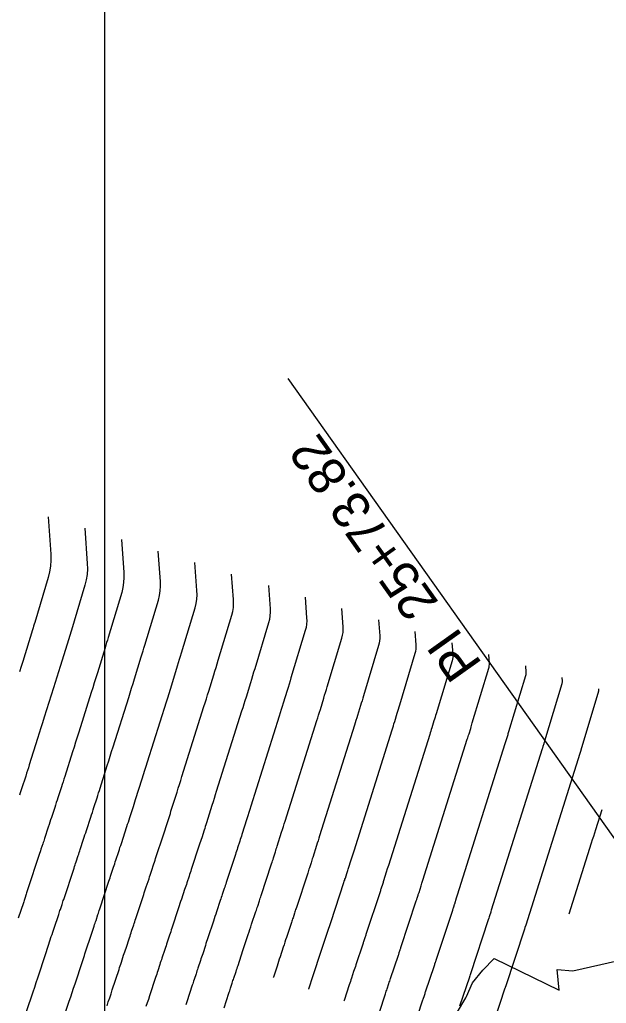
# Model space of a CAD drawing. Extents: x 1710723 to 1713003, y 548603 to 551142.
# Drawn here: x 1712348 to 1712442.1, y 549743.8 to 549901.4 of the extents above; entities that cross this region are included whole.
import ezdxf

# ---------------------------------------------------------------- set-up
doc = ezdxf.new("R2010")
doc.units = 0
for name, color, linetype in [('R_Contours', 7, 'Continuous'), ('R_Horz Alg Annot', 7, 'Continuous'), ('R_MOT', 7, 'Continuous'), ('R_No Plot', 7, 'Continuous')]:
    doc.layers.add(name, color=color, linetype=linetype)

msp = doc.modelspace()

# ---------------------------------------------------------------- linework, layer by layer
at = {"layer": 'R_Contours'}
for points in [[(1712352.55, 549821.78), (1712352.99, 549815.75), (1712353.02, 549814.8), (1712352.96, 549813.87), (1712352.81, 549812.95), (1712352.58, 549812.03), (1712350.42, 549804.83), (1712350.33, 549804.54), (1712350.24, 549804.25), (1712350.15, 549803.96), (1712350.06, 549803.67), (1712348.5, 549798.6), (1712348.24, 549797.76), (1712347.98, 549796.92)], [(1712358.44, 549819.94), (1712358.85, 549814.3), (1712358.88, 549813.41), (1712358.82, 549812.54), (1712358.68, 549811.68), (1712358.47, 549810.82), (1712356.3, 549803.62), (1712356.2, 549803.27), (1712356.09, 549802.93), (1712355.99, 549802.58), (1712355.88, 549802.23), (1712354.5, 549797.77), (1712354.24, 549796.91), (1712353.97, 549796.05), (1712353.7, 549795.2), (1712353.43, 549794.34), (1712351.95, 549789.64), (1712351.68, 549788.78), (1712351.41, 549787.93), (1712351.14, 549787.08), (1712350.87, 549786.23), (1712349.54, 549782.02), (1712349.4, 549781.57), (1712349.26, 549781.12), (1712349.12, 549780.67), (1712348.97, 549780.22), (1712348.32, 549778.19), (1712348.21, 549777.85), (1712348.1, 549777.52), (1712347.99, 549777.19)], [(1712364.32, 549818.1), (1712364.71, 549812.85), (1712364.73, 549812.02), (1712364.68, 549811.21), (1712364.56, 549810.41), (1712364.36, 549809.61), (1712362.19, 549802.41), (1712362.07, 549802), (1712361.94, 549801.6), (1712361.82, 549801.19), (1712361.69, 549800.78), (1712360.46, 549796.79), (1712360.22, 549795.99), (1712359.97, 549795.19), (1712359.72, 549794.39), (1712359.47, 549793.59), (1712357.47, 549787.26), (1712357.22, 549786.47), (1712356.97, 549785.67), (1712356.72, 549784.88), (1712356.47, 549784.09), (1712355.23, 549780.16), (1712355.09, 549779.74), (1712354.96, 549779.32), (1712354.83, 549778.9), (1712354.69, 549778.48), (1712354.14, 549776.75), (1712354.01, 549776.36), (1712353.88, 549775.97), (1712353.75, 549775.58), (1712353.63, 549775.18), (1712353.1, 549773.59), (1712352.97, 549773.21), (1712352.85, 549772.83), (1712352.72, 549772.45), (1712352.6, 549772.07), (1712352, 549770.22), (1712351.93, 549770.01), (1712351.86, 549769.79), (1712351.79, 549769.58), (1712351.71, 549769.36), (1712351.42, 549768.5), (1712351.35, 549768.28), (1712351.28, 549768.07), (1712351.21, 549767.85), (1712351.14, 549767.64), (1712349.28, 549762.02), (1712349.22, 549761.85), (1712349.17, 549761.67), (1712349.11, 549761.5), (1712349.05, 549761.32), (1712348.83, 549760.63), (1712348.77, 549760.45), (1712348.71, 549760.28), (1712348.65, 549760.1), (1712348.6, 549759.93), (1712347.77, 549757.48)], [(1712348.84, 549741.77), (1712349.9, 549744.89), (1712350.15, 549745.65), (1712350.41, 549746.4), (1712350.66, 549747.16), (1712350.91, 549747.92), (1712352.2, 549751.81), (1712352.31, 549752.15), (1712352.42, 549752.49), (1712352.53, 549752.82), (1712352.64, 549753.16), (1712353.08, 549754.52), (1712353.2, 549754.86), (1712353.31, 549755.2), (1712353.42, 549755.54), (1712353.53, 549755.88), (1712354.27, 549758.07), (1712354.34, 549758.27), (1712354.4, 549758.47), (1712354.47, 549758.67), (1712354.54, 549758.87), (1712354.8, 549759.68), (1712354.86, 549759.88), (1712354.93, 549760.08), (1712355, 549760.28), (1712355.06, 549760.48), (1712356.72, 549765.5), (1712356.8, 549765.75), (1712356.89, 549766), (1712356.97, 549766.25), (1712357.05, 549766.5), (1712357.39, 549767.49), (1712357.47, 549767.74), (1712357.55, 549767.99), (1712357.63, 549768.24), (1712357.72, 549768.49), (1712358.24, 549770.1), (1712358.36, 549770.45), (1712358.47, 549770.81), (1712358.59, 549771.16), (1712358.7, 549771.51), (1712359.41, 549773.64), (1712359.53, 549774.03), (1712359.66, 549774.42), (1712359.79, 549774.8), (1712359.91, 549775.19), (1712360.41, 549776.75), (1712360.54, 549777.14), (1712360.66, 549777.52), (1712360.78, 549777.91), (1712360.91, 549778.3), (1712362.06, 549781.94), (1712362.29, 549782.68), (1712362.52, 549783.42), (1712362.75, 549784.15), (1712362.99, 549784.89), (1712365.5, 549792.84), (1712365.73, 549793.58), (1712365.96, 549794.33), (1712366.19, 549795.07), (1712366.42, 549795.81), (1712367.51, 549799.34), (1712367.65, 549799.8), (1712367.79, 549800.27), (1712367.94, 549800.73), (1712368.08, 549801.2), (1712370.24, 549808.4), (1712370.43, 549809.14), (1712370.55, 549809.88), (1712370.59, 549810.63), (1712370.57, 549811.39), (1712370.21, 549816.26)], [(1712354.98, 549741.3), (1712355.95, 549744.17), (1712356.19, 549744.87), (1712356.42, 549745.57), (1712356.66, 549746.26), (1712356.89, 549746.96), (1712358.07, 549750.53), (1712358.17, 549750.85), (1712358.27, 549751.16), (1712358.38, 549751.47), (1712358.48, 549751.78), (1712358.88, 549753.03), (1712358.98, 549753.34), (1712359.09, 549753.65), (1712359.19, 549753.96), (1712359.29, 549754.27), (1712359.94, 549756.2), (1712360.02, 549756.43), (1712360.1, 549756.66), (1712360.17, 549756.89), (1712360.25, 549757.11), (1712360.54, 549758.03), (1712360.62, 549758.26), (1712360.69, 549758.49), (1712360.77, 549758.72), (1712360.84, 549758.94), (1712362.31, 549763.37), (1712362.4, 549763.65), (1712362.49, 549763.93), (1712362.59, 549764.22), (1712362.68, 549764.5), (1712363.06, 549765.62), (1712363.15, 549765.9), (1712363.25, 549766.19), (1712363.34, 549766.47), (1712363.43, 549766.75), (1712363.88, 549768.13), (1712363.99, 549768.46), (1712364.09, 549768.78), (1712364.2, 549769.1), (1712364.31, 549769.43), (1712365.21, 549772.15), (1712365.32, 549772.51), (1712365.44, 549772.86), (1712365.56, 549773.22), (1712365.67, 549773.58), (1712366.13, 549775.01), (1712366.25, 549775.37), (1712366.36, 549775.73), (1712366.48, 549776.09), (1712366.59, 549776.45), (1712367.65, 549779.8), (1712367.86, 549780.48), (1712368.08, 549781.16), (1712368.29, 549781.84), (1712368.5, 549782.52), (1712371.53, 549792.1), (1712371.74, 549792.78), (1712371.96, 549793.46), (1712372.17, 549794.15), (1712372.38, 549794.83), (1712373.33, 549797.89), (1712373.49, 549798.42), (1712373.65, 549798.94), (1712373.81, 549799.46), (1712373.96, 549799.99), (1712376.13, 549807.19), (1712376.3, 549807.87), (1712376.41, 549808.55), (1712376.45, 549809.24), (1712376.43, 549809.94), (1712376.1, 549814.42)], [(1712362.01, 549743.45), (1712362.22, 549744.09), (1712362.44, 549744.73), (1712362.65, 549745.36), (1712362.86, 549746), (1712363.94, 549749.26), (1712364.03, 549749.54), (1712364.13, 549749.83), (1712364.22, 549750.11), (1712364.31, 549750.4), (1712364.68, 549751.54), (1712364.77, 549751.82), (1712364.87, 549752.1), (1712364.96, 549752.39), (1712365.06, 549752.67), (1712365.62, 549754.33), (1712365.7, 549754.59), (1712365.79, 549754.85), (1712365.87, 549755.1), (1712365.96, 549755.36), (1712366.29, 549756.38), (1712366.37, 549756.64), (1712366.46, 549756.9), (1712366.54, 549757.15), (1712366.62, 549757.41), (1712367.89, 549761.24), (1712367.99, 549761.55), (1712368.1, 549761.87), (1712368.2, 549762.18), (1712368.31, 549762.5), (1712368.75, 549763.79), (1712368.84, 549764.09), (1712368.94, 549764.38), (1712369.04, 549764.68), (1712369.14, 549764.98), (1712369.52, 549766.16), (1712369.62, 549766.46), (1712369.72, 549766.75), (1712369.81, 549767.05), (1712369.91, 549767.34), (1712371.01, 549770.66), (1712371.11, 549770.98), (1712371.22, 549771.31), (1712371.33, 549771.64), (1712371.43, 549771.97), (1712371.85, 549773.28), (1712371.96, 549773.6), (1712372.06, 549773.93), (1712372.17, 549774.26), (1712372.27, 549774.59), (1712373.24, 549777.66), (1712373.44, 549778.28), (1712373.63, 549778.9), (1712373.83, 549779.52), (1712374.02, 549780.14), (1712377.56, 549791.35), (1712377.76, 549791.97), (1712377.95, 549792.6), (1712378.15, 549793.23), (1712378.34, 549793.85), (1712379.14, 549796.45), (1712379.32, 549797.03), (1712379.5, 549797.61), (1712379.67, 549798.19), (1712379.85, 549798.78), (1712382.02, 549805.98), (1712382.17, 549806.6), (1712382.27, 549807.22), (1712382.31, 549807.85), (1712382.29, 549808.49), (1712381.99, 549812.58)], [(1712387.88, 549810.75), (1712388.15, 549807.04), (1712388.17, 549806.46), (1712388.13, 549805.89), (1712388.04, 549805.32), (1712387.9, 549804.76), (1712385.69, 549797.42), (1712385.52, 549796.85), (1712385.35, 549796.28), (1712385.18, 549795.71), (1712385, 549795.14), (1712384.3, 549792.87), (1712384.12, 549792.3), (1712383.95, 549791.74), (1712383.77, 549791.17), (1712383.59, 549790.6), (1712379.54, 549777.77), (1712379.36, 549777.21), (1712379.19, 549776.64), (1712379.01, 549776.08), (1712378.83, 549775.52), (1712377.95, 549772.73), (1712377.86, 549772.43), (1712377.76, 549772.14), (1712377.67, 549771.84), (1712377.57, 549771.54), (1712377.19, 549770.35), (1712377.1, 549770.06), (1712377, 549769.76), (1712376.9, 549769.46), (1712376.8, 549769.17), (1712375.51, 549765.26), (1712375.43, 549764.99), (1712375.34, 549764.73), (1712375.25, 549764.46), (1712375.16, 549764.19), (1712374.81, 549763.12), (1712374.73, 549762.85), (1712374.64, 549762.58), (1712374.55, 549762.31), (1712374.46, 549762.05), (1712373.94, 549760.5), (1712373.82, 549760.15), (1712373.71, 549759.8), (1712373.59, 549759.45), (1712373.48, 549759.11), (1712372.41, 549755.87), (1712372.31, 549755.59), (1712372.22, 549755.3), (1712372.13, 549755.02), (1712372.03, 549754.74), (1712371.66, 549753.6), (1712371.57, 549753.32), (1712371.48, 549753.04), (1712371.38, 549752.75), (1712371.29, 549752.47), (1712370.82, 549751.07), (1712370.73, 549750.81), (1712370.65, 549750.56), (1712370.56, 549750.3), (1712370.48, 549750.04), (1712370.14, 549749.01), (1712370.06, 549748.76), (1712369.98, 549748.5), (1712369.89, 549748.24), (1712369.81, 549747.99), (1712368.83, 549745.04), (1712368.64, 549744.46), (1712368.45, 549743.89), (1712368.26, 549743.31)], [(1712393.77, 549808.91), (1712394.01, 549805.59), (1712394.03, 549805.07), (1712394, 549804.56), (1712393.92, 549804.05), (1712393.79, 549803.55), (1712391.51, 549795.97), (1712391.36, 549795.46), (1712391.2, 549794.95), (1712391.05, 549794.44), (1712390.89, 549793.93), (1712390.26, 549791.89), (1712390.1, 549791.38), (1712389.94, 549790.87), (1712389.78, 549790.36), (1712389.62, 549789.85), (1712385.06, 549775.4), (1712384.9, 549774.89), (1712384.74, 549774.39), (1712384.58, 549773.88), (1712384.42, 549773.38), (1712383.63, 549770.88), (1712383.55, 549770.61), (1712383.46, 549770.34), (1712383.38, 549770.07), (1712383.29, 549769.81), (1712382.95, 549768.74), (1712382.86, 549768.47), (1712382.78, 549768.21), (1712382.69, 549767.94), (1712382.6, 549767.67), (1712381.12, 549763.18), (1712381.04, 549762.94), (1712380.96, 549762.7), (1712380.88, 549762.46), (1712380.8, 549762.22), (1712380.49, 549761.26), (1712380.41, 549761.02), (1712380.33, 549760.78), (1712380.25, 549760.54), (1712380.17, 549760.3), (1712379.57, 549758.5), (1712379.44, 549758.12), (1712379.31, 549757.74), (1712379.19, 549757.36), (1712379.06, 549756.97), (1712378.19, 549754.33), (1712378.08, 549754.02), (1712377.98, 549753.71), (1712377.88, 549753.4), (1712377.78, 549753.09), (1712377.35, 549751.78), (1712377.26, 549751.5), (1712377.17, 549751.22), (1712377.08, 549750.95), (1712376.99, 549750.67), (1712376.58, 549749.47), (1712376.5, 549749.24), (1712376.43, 549749.01), (1712376.35, 549748.78), (1712376.28, 549748.55), (1712375.98, 549747.63), (1712375.9, 549747.4), (1712375.83, 549747.17), (1712375.75, 549746.94), (1712375.68, 549746.71), (1712374.81, 549744.08), (1712374.64, 549743.56)], [(1712380.78, 549743.12), (1712381.55, 549745.44), (1712381.61, 549745.64), (1712381.68, 549745.84), (1712381.75, 549746.04), (1712381.81, 549746.25), (1712382.08, 549747.06), (1712382.14, 549747.26), (1712382.21, 549747.46), (1712382.28, 549747.66), (1712382.34, 549747.87), (1712382.7, 549748.93), (1712382.78, 549749.17), (1712382.86, 549749.41), (1712382.94, 549749.66), (1712383.02, 549749.9), (1712383.52, 549751.44), (1712383.63, 549751.78), (1712383.75, 549752.12), (1712383.86, 549752.46), (1712383.97, 549752.79), (1712384.64, 549754.84), (1712384.78, 549755.26), (1712384.92, 549755.67), (1712385.06, 549756.08), (1712385.2, 549756.5), (1712385.89, 549758.55), (1712385.96, 549758.76), (1712386.03, 549758.97), (1712386.1, 549759.19), (1712386.17, 549759.4), (1712386.44, 549760.25), (1712386.51, 549760.46), (1712386.58, 549760.67), (1712386.65, 549760.89), (1712386.72, 549761.1), (1712388.4, 549766.18), (1712388.48, 549766.42), (1712388.56, 549766.65), (1712388.63, 549766.89), (1712388.71, 549767.13), (1712389.01, 549768.07), (1712389.09, 549768.31), (1712389.16, 549768.55), (1712389.24, 549768.78), (1712389.31, 549769.02), (1712390.01, 549771.23), (1712390.16, 549771.68), (1712390.3, 549772.13), (1712390.44, 549772.58), (1712390.58, 549773.03), (1712395.66, 549789.11), (1712395.8, 549789.56), (1712395.94, 549790.01), (1712396.08, 549790.46), (1712396.22, 549790.91), (1712396.78, 549792.72), (1712396.91, 549793.17), (1712397.05, 549793.62), (1712397.19, 549794.08), (1712397.33, 549794.53), (1712399.68, 549802.34), (1712399.79, 549802.78), (1712399.86, 549803.23), (1712399.89, 549803.68), (1712399.87, 549804.14), (1712399.66, 549807.07)], [(1712405.55, 549805.23), (1712405.74, 549802.69), (1712405.75, 549802.29), (1712405.72, 549801.9), (1712405.66, 549801.51), (1712405.56, 549801.13), (1712403.14, 549793.08), (1712403.02, 549792.69), (1712402.9, 549792.3), (1712402.78, 549791.9), (1712402.66, 549791.51), (1712402.18, 549789.93), (1712402.06, 549789.54), (1712401.93, 549789.15), (1712401.81, 549788.75), (1712401.69, 549788.36), (1712396.1, 549770.65), (1712395.97, 549770.26), (1712395.85, 549769.87), (1712395.73, 549769.48), (1712395.61, 549769.09), (1712395, 549767.16), (1712394.93, 549766.96), (1712394.87, 549766.75), (1712394.8, 549766.54), (1712394.73, 549766.34), (1712394.47, 549765.51), (1712394.4, 549765.31), (1712394.34, 549765.1), (1712394.27, 549764.9), (1712394.2, 549764.69), (1712392.32, 549759.01), (1712392.26, 549758.83), (1712392.2, 549758.65), (1712392.14, 549758.46), (1712392.08, 549758.28), (1712391.84, 549757.54), (1712391.78, 549757.36), (1712391.72, 549757.17), (1712391.66, 549756.99), (1712391.6, 549756.8), (1712390.78, 549754.37), (1712390.65, 549753.99), (1712390.53, 549753.6), (1712390.4, 549753.22), (1712390.27, 549752.83), (1712389.75, 549751.26), (1712389.63, 549750.89), (1712389.51, 549750.53), (1712389.39, 549750.16), (1712389.27, 549749.8), (1712388.69, 549748.03), (1712388.68, 549747.97)], [(1712394.34, 549746.08), (1712394.36, 549746.15), (1712395.06, 549748.28), (1712395.16, 549748.61), (1712395.27, 549748.94), (1712395.38, 549749.26), (1712395.49, 549749.59), (1712395.92, 549750.89), (1712396.02, 549751.21), (1712396.13, 549751.54), (1712396.24, 549751.86), (1712396.35, 549752.19), (1712397.31, 549755.06), (1712397.37, 549755.21), (1712397.42, 549755.37), (1712397.47, 549755.53), (1712397.52, 549755.68), (1712397.72, 549756.31), (1712397.77, 549756.46), (1712397.83, 549756.62), (1712397.88, 549756.78), (1712397.93, 549756.93), (1712400, 549763.2), (1712400.06, 549763.37), (1712400.12, 549763.55), (1712400.17, 549763.72), (1712400.23, 549763.9), (1712400.45, 549764.6), (1712400.51, 549764.78), (1712400.57, 549764.95), (1712400.62, 549765.13), (1712400.68, 549765.3), (1712401.2, 549766.95), (1712401.3, 549767.28), (1712401.41, 549767.61), (1712401.51, 549767.95), (1712401.62, 549768.28), (1712407.72, 549787.61), (1712407.82, 549787.95), (1712407.93, 549788.28), (1712408.03, 549788.62), (1712408.14, 549788.95), (1712408.55, 549790.3), (1712408.65, 549790.63), (1712408.76, 549790.97), (1712408.86, 549791.3), (1712408.96, 549791.64), (1712411.45, 549799.92), (1712411.53, 549800.24), (1712411.58, 549800.57), (1712411.61, 549800.9), (1712411.6, 549801.24), (1712411.44, 549803.39)], [(1712417.33, 549801.55), (1712417.46, 549799.79), (1712417.46, 549799.51), (1712417.45, 549799.24), (1712417.41, 549798.97), (1712417.34, 549798.71), (1712414.78, 549790.19), (1712414.69, 549789.92), (1712414.61, 549789.64), (1712414.52, 549789.36), (1712414.44, 549789.08), (1712414.1, 549787.97), (1712414.01, 549787.7), (1712413.92, 549787.42), (1712413.84, 549787.14), (1712413.75, 549786.87), (1712407.14, 549765.91), (1712406.96, 549765.36), (1712406.79, 549764.81), (1712406.36, 549763.45), (1712406.31, 549763.3), (1712406.27, 549763.16), (1712406.22, 549763.01), (1712406.17, 549762.87), (1712405.99, 549762.29), (1712405.94, 549762.14), (1712405.89, 549762), (1712405.85, 549761.85), (1712405.8, 549761.71), (1712403.53, 549754.85), (1712403.49, 549754.72), (1712403.45, 549754.59), (1712403.41, 549754.46), (1712403.36, 549754.34), (1712403.2, 549753.82), (1712403.16, 549753.69), (1712403.11, 549753.57), (1712403.07, 549753.44), (1712403.03, 549753.31), (1712401.92, 549750), (1712401.83, 549749.74), (1712401.74, 549749.47), (1712401.65, 549749.2), (1712401.56, 549748.94), (1712401.21, 549747.88), (1712401.12, 549747.61), (1712401.03, 549747.34), (1712400.95, 549747.08), (1712400.86, 549746.81), (1712400.03, 549744.27), (1712400.01, 549744.19)], [(1712405.71, 549742.4), (1712406.66, 549745.34), (1712406.73, 549745.54), (1712406.8, 549745.75), (1712406.87, 549745.96), (1712406.93, 549746.16), (1712407.21, 549746.99), (1712407.27, 549747.2), (1712407.34, 549747.4), (1712407.41, 549747.61), (1712407.48, 549747.82), (1712408.74, 549751.56), (1712408.78, 549751.66), (1712408.81, 549751.76), (1712408.84, 549751.86), (1712408.87, 549751.96), (1712409, 549752.37), (1712409.04, 549752.47), (1712409.07, 549752.57), (1712409.1, 549752.67), (1712409.14, 549752.77), (1712411.6, 549760.22), (1712411.64, 549760.33), (1712411.67, 549760.44), (1712411.71, 549760.56), (1712411.75, 549760.67), (1712411.89, 549761.13), (1712411.93, 549761.25), (1712411.97, 549761.36), (1712412, 549761.48), (1712412.04, 549761.59), (1712412.38, 549762.67), (1712412.52, 549763.1), (1712412.65, 549763.53), (1712419.78, 549786.12), (1712419.85, 549786.34), (1712419.92, 549786.56), (1712419.99, 549786.78), (1712420.06, 549786.99), (1712420.33, 549787.87), (1712420.39, 549788.09), (1712420.46, 549788.31), (1712420.53, 549788.53), (1712420.59, 549788.75), (1712423.22, 549797.49), (1712423.28, 549797.7), (1712423.31, 549797.91), (1712423.32, 549798.12), (1712423.32, 549798.34), (1712423.22, 549799.71)], [(1712429.11, 549797.87), (1712429.18, 549796.89), (1712429.18, 549796.73), (1712429.17, 549796.58), (1712429.15, 549796.43), (1712429.11, 549796.28), (1712426.41, 549787.3), (1712426.36, 549787.14), (1712426.31, 549786.98), (1712426.26, 549786.82), (1712426.21, 549786.66), (1712426.02, 549786.01), (1712425.97, 549785.85), (1712425.92, 549785.69), (1712425.87, 549785.53), (1712425.81, 549785.37), (1712418.17, 549761.16), (1712418.02, 549760.68), (1712417.72, 549759.73), (1712417.7, 549759.65), (1712417.67, 549759.57), (1712417.64, 549759.48), (1712417.61, 549759.4), (1712417.51, 549759.06), (1712417.48, 549758.98), (1712417.45, 549758.89), (1712417.42, 549758.81), (1712417.4, 549758.72), (1712414.74, 549750.68), (1712414.72, 549750.61), (1712414.69, 549750.54), (1712414.67, 549750.47), (1712414.64, 549750.39), (1712414.55, 549750.11), (1712414.53, 549750.03), (1712414.5, 549749.96), (1712414.48, 549749.89), (1712414.46, 549749.82), (1712413.05, 549745.63), (1712413, 549745.49), (1712412.95, 549745.34), (1712412.9, 549745.19), (1712412.85, 549745.04), (1712412.66, 549744.45), (1712412.61, 549744.31), (1712412.56, 549744.16), (1712412.51, 549744.01), (1712412.46, 549743.86), (1712411.38, 549740.52)], [(1712418.61, 549743.45), (1712420.17, 549748.07), (1712420.18, 549748.11), (1712420.2, 549748.16), (1712420.21, 549748.2), (1712420.23, 549748.25), (1712420.29, 549748.42), (1712420.3, 549748.47), (1712420.31, 549748.51), (1712420.33, 549748.56), (1712420.34, 549748.6), (1712423.2, 549757.23), (1712423.21, 549757.29), (1712423.23, 549757.34), (1712423.25, 549757.39), (1712423.27, 549757.45), (1712423.34, 549757.66), (1712423.35, 549757.72), (1712423.37, 549757.77), (1712423.39, 549757.82), (1712423.4, 549757.88), (1712423.59, 549758.48), (1712423.69, 549758.79), (1712431.85, 549784.62), (1712431.88, 549784.73), (1712431.91, 549784.83), (1712431.94, 549784.93), (1712431.97, 549785.04), (1712432.1, 549785.45), (1712432.13, 549785.55), (1712432.16, 549785.65), (1712432.2, 549785.75), (1712432.23, 549785.86), (1712435, 549795.07), (1712435.02, 549795.16), (1712435.04, 549795.25), (1712435.04, 549795.34), (1712435.04, 549795.44), (1712435, 549796.03)], [(1712424.18, 549741.26), (1712425.88, 549746.32), (1712425.89, 549746.36), (1712425.9, 549746.39), (1712425.93, 549746.47), (1712425.94, 549746.5), (1712425.95, 549746.52), (1712429, 549755.74), (1712429, 549755.76), (1712429.01, 549755.79), (1712429.02, 549755.81), (1712429.03, 549755.83), (1712429.06, 549755.93), (1712429.07, 549755.97), (1712429.09, 549756.02), (1712429.21, 549756.42), (1712437.88, 549783.88), (1712437.89, 549783.92), (1712437.91, 549783.97), (1712437.92, 549784.01), (1712437.93, 549784.06), (1712437.99, 549784.23), (1712438, 549784.28), (1712438.02, 549784.32), (1712438.03, 549784.37), (1712438.04, 549784.41), (1712440.89, 549793.86), (1712440.89, 549793.89), (1712440.9, 549793.92), (1712440.9, 549793.95), (1712440.9, 549793.99), (1712440.88, 549794.19)], [(1712441.35, 549774.83), (1712440.34, 549771.63), (1712440.17, 549771.1), (1712440, 549770.56), (1712439.83, 549770.03), (1712439.67, 549769.5), (1712436.05, 549758.12)]]:
    msp.add_lwpolyline(points, dxfattribs=at)
at = {"layer": 'R_Horz Alg Annot'}
msp.add_lwpolyline([(1712460.53, 549746.07), (1712391.04, 549843.91)], dxfattribs=at)
at = {"layer": 'R_MOT'}
for points in [[(1712436.73, 549749.05), (1712482.53, 549759.39), (1712513.12, 549759.39), (1712541.71, 549760.22), (1712541.93, 549758.2)], [(1712418.22, 549742.48), (1712419.54, 549744.71), (1712419.66, 549744.9), (1712420.64, 549747.11), (1712422.28, 549749.15), (1712424.1, 549751.03), (1712434.51, 549745.95), (1712434.18, 549749.22), (1712436.73, 549749.05)]]:
    msp.add_lwpolyline(points, dxfattribs=at)
at = {"layer": 'R_No Plot'}
msp.add_lwpolyline([(1712635.83, 549942.65), (1712361.6, 549942.65), (1712361.6, 549562.59)], dxfattribs=at)

# ---------------------------------------------------------------- texts
at = {"layer": 'R_Horz Alg Annot'}
msp.add_text('PI  25+73.82', height=6, rotation=125.3867, dxfattribs=at).set_placement((1712422.29, 549798.19))

doc.saveas('drawing.dxf')
